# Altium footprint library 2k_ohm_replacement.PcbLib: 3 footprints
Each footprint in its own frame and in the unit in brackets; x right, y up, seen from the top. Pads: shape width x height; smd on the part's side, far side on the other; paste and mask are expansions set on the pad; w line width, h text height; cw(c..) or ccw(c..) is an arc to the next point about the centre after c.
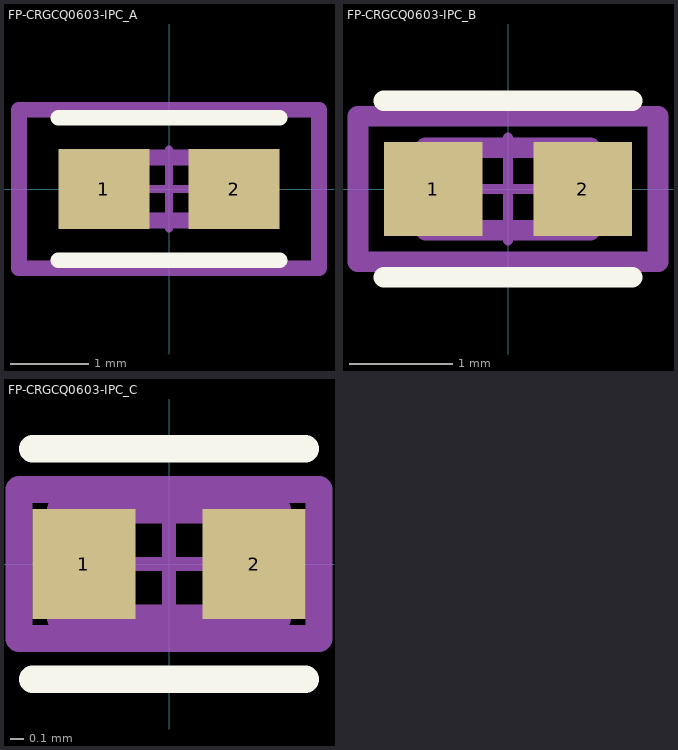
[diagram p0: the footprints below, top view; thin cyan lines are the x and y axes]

## FP-CRGCQ0603-IPC_A [mm]
pads (2):
  rect 1.158x1.012 smd paste+0 mask+0: 1(-0.827,0) 2(0.827,0)
Top Overlay:
  lines w0.2: -1.406,-0.906 1.406,-0.906 ; -1.406,0.906 1.406,0.906
Mechanical 5:
  lines w0.2: -1.906,-1.006 1.906,-1.006 1.906,1.006 -1.906,1.006 -1.906,-1.006
  text ".Designator" at 0,0.188 h1
Mechanical 13:
  lines w0.2: -0.8,-0.4 0.8,-0.4 0.8,0.4 -0.8,0.4 -0.8,-0.4
Mechanical 15:
  lines w0.2: -1.906,-1.006 1.906,-1.006 1.906,1.006 -1.906,1.006 -1.906,-1.006
Mechanical 16:
  lines w0.1: -0.5,0 0.5,0 ; 0,-0.5 0,0.5
3D body "Res_TE_Connectivity_CRGCQ0603F12R_eec.STEP": height 0.25, standoff 0, extent -1.906,-1.006 1.906,1.006

## FP-CRGCQ0603-IPC_B [mm]
pads (2):
  rect 0.958x0.912 smd paste+0 mask+0: 1(-0.727,0) 2(0.727,0)
Top Overlay:
  lines w0.2: -1.206,-0.856 1.206,-0.856 ; -1.206,0.856 1.206,0.856
Mechanical 5:
  lines w0.2: -1.456,-0.706 1.456,-0.706 1.456,0.706 -1.456,0.706 -1.456,-0.706
  text ".Designator" at 0,0.188 h1
Mechanical 13:
  lines w0.2: -0.8,-0.4 0.8,-0.4 0.8,0.4 -0.8,0.4 -0.8,-0.4
Mechanical 15:
  lines w0.2: -1.456,-0.706 1.456,-0.706 1.456,0.706 -1.456,0.706 -1.456,-0.706
Mechanical 16:
  lines w0.1: -0.5,0 0.5,0 ; 0,-0.5 0,0.5
3D body "Res_TE_Connectivity_CRGCQ0603F12R_eec.STEP": height 0.25, standoff 0, extent -1.456,-0.706 1.456,0.706

## FP-CRGCQ0603-IPC_C [mm]
pads (2):
  rect 0.758x0.812 smd paste+0 mask+0: 1(-0.627,0) 2(0.627,0)
Top Overlay:
  lines w0.2: -1.006,-0.85 1.006,-0.85 ; -1.006,0.85 1.006,0.85
Mechanical 5:
  lines w0.2: -1.106,-0.55 1.106,-0.55 1.106,0.55 -1.106,0.55 -1.106,-0.55
  text ".Designator" at 0,0.188 h1
Mechanical 13:
  lines w0.2: -0.8,-0.4 0.8,-0.4 0.8,0.4 -0.8,0.4 -0.8,-0.4
Mechanical 15:
  lines w0.2: -1.106,-0.55 1.106,-0.55 1.106,0.55 -1.106,0.55 -1.106,-0.55
Mechanical 16:
  lines w0.1: -0.5,0 0.5,0 ; 0,-0.5 0,0.5
3D body "Res_TE_Connectivity_CRGCQ0603F12R_eec.STEP": height 0.25, standoff 0, extent -1.106,-0.55 1.106,0.55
